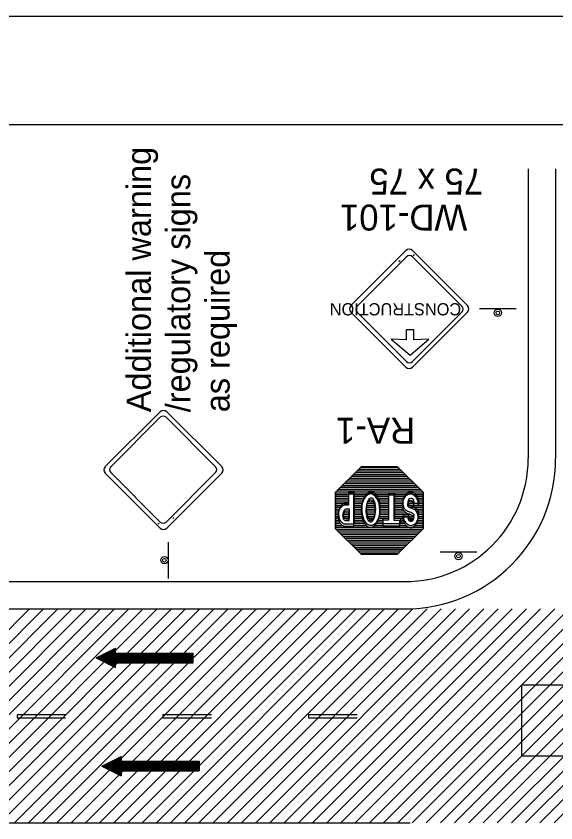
# Model space of a CAD drawing. Extents: x 2111 to 2327, y 208 to 487.
# Drawn here: x 2160.6 to 2214.3, y 406.9 to 487.2 of the extents above; entities that cross this region are included whole.
import ezdxf

# ---------------------------------------------------------------- set-up
doc = ezdxf.new("R2010")
doc.units = 0
for name, color, linetype in [('Level 10', 7, 'Continuous'), ('Level 2', 7, 'Continuous'), ('Level 44', 7, 'Continuous'), ('Level 60', 7, 'Continuous')]:
    doc.layers.add(name, color=color, linetype=linetype)

msp = doc.modelspace()

# ---------------------------------------------------------------- linework, layer by layer
at = {"layer": 'Level 10'}
for p, q in [((2211.547, 472.013), (2211.547, 443.162)), ((2214.274, 472.013), (2214.274, 443.162)), ((2140.664, 430.889), (2199.274, 430.889)), ((2140.664, 428.162), (2199.274, 428.162)), ((2140.664, 406.949), (2161.877, 428.162)), ((2141.991, 406.862), (2163.291, 428.162)), ((2143.406, 406.862), (2164.706, 428.162)), ((2144.82, 406.862), (2166.12, 428.162)), ((2146.234, 406.862), (2167.534, 428.162)), ((2147.649, 406.862), (2168.948, 428.162)), ((2149.063, 406.862), (2170.362, 428.162)), ((2150.477, 406.863), (2171.777, 428.162)), ((2151.892, 406.863), (2173.191, 428.162)), ((2153.306, 406.863), (2174.605, 428.162)), ((2154.72, 406.863), (2176.019, 428.162)), ((2156.134, 406.863), (2177.434, 428.162)), ((2157.549, 406.863), (2178.848, 428.162)), ((2158.963, 406.863), (2180.262, 428.162)), ((2160.377, 406.863), (2181.676, 428.162)), ((2161.792, 406.863), (2183.09, 428.162)), ((2163.206, 406.863), (2184.505, 428.162)), ((2164.62, 406.863), (2185.919, 428.162)), ((2166.034, 406.863), (2187.333, 428.162)), ((2167.449, 406.864), (2188.747, 428.162)), ((2168.863, 406.864), (2190.161, 428.162)), ((2170.277, 406.864), (2191.576, 428.162)), ((2171.692, 406.864), (2192.99, 428.162)), ((2173.106, 406.864), (2194.404, 428.162)), ((2174.52, 406.864), (2195.818, 428.162)), ((2175.935, 406.864), (2197.233, 428.162)), ((2177.349, 406.864), (2198.647, 428.162)), ((2178.763, 406.864), (2200.061, 428.162)), ((2180.177, 406.864), (2201.475, 428.162)), ((2181.592, 406.864), (2202.889, 428.162)), ((2183.006, 406.864), (2204.304, 428.162)), ((2184.42, 406.864), (2205.718, 428.162)), ((2185.835, 406.865), (2207.132, 428.162)), ((2187.249, 406.865), (2208.546, 428.162)), ((2188.663, 406.865), (2209.96, 428.162)), ((2190.077, 406.865), (2211.375, 428.162)), ((2191.492, 406.865), (2212.789, 428.162)), ((2192.906, 406.865), (2214.203, 428.162)), ((2194.32, 406.865), (2215.617, 428.162)), ((2195.735, 406.865), (2217.032, 428.162)), ((2197.149, 406.865), (2218.446, 428.162)), ((2198.563, 406.865), (2219.86, 428.162)), ((2199.978, 406.865), (2221.274, 428.162)), ((2201.392, 406.865), (2222.688, 428.162)), ((2202.806, 406.865), (2224.103, 428.162)), ((2204.22, 406.866), (2225.517, 428.162)), ((2205.635, 406.866), (2226.931, 428.162)), ((2207.049, 406.866), (2228.345, 428.162)), ((2208.463, 406.866), (2229.759, 428.162)), ((2209.878, 406.866), (2231.174, 428.162)), ((2211.292, 406.866), (2232.588, 428.162)), ((2212.706, 406.866), (2234.002, 428.162)), ((2214.12, 406.866), (2235.416, 428.162)), ((2168.514, 423.287), (2170.45, 424.255)), ((2170.45, 423.772), (2170.45, 424.255)), ((2168.999, 423.528), (2178.192, 423.528)), ((2169.241, 423.651), (2178.192, 423.651)), ((2169.482, 423.772), (2178.192, 423.772)), ((2169.724, 423.891), (2170.45, 423.891)), ((2169.966, 424.014), (2170.45, 424.014)), ((2170.208, 424.134), (2170.45, 424.134)), ((2170.45, 423.772), (2178.192, 423.772)), ((2178.192, 422.803), (2178.192, 423.772)), ((2168.514, 423.287), (2178.192, 423.287)), ((2168.514, 423.287), (2170.45, 422.32)), ((2168.757, 423.408), (2178.192, 423.408)), ((2168.757, 423.166), (2178.192, 423.166)), ((2168.999, 423.045), (2178.192, 423.045)), ((2169.241, 422.924), (2178.192, 422.924)), ((2169.482, 422.803), (2178.192, 422.803)), ((2169.724, 422.682), (2170.45, 422.682)), ((2170.45, 422.803), (2178.192, 422.803)), ((2170.45, 422.32), (2170.45, 422.803)), ((2169.966, 422.561), (2170.45, 422.561)), ((2170.208, 422.44), (2170.45, 422.44)), ((2169.092, 412.517), (2171.029, 413.486)), ((2170.06, 413), (2178.77, 413)), ((2170.302, 413.121), (2171.029, 413.121)), ((2170.544, 413.242), (2171.029, 413.242)), ((2170.785, 413.363), (2171.029, 413.363)), ((2171.029, 413.486), (2171.029, 413)), ((2171.029, 413), (2178.77, 413)), ((2178.77, 413), (2178.77, 412.033)), ((2169.092, 412.517), (2178.77, 412.517)), ((2169.092, 412.517), (2171.029, 411.548)), ((2169.335, 412.638), (2178.77, 412.638)), ((2169.335, 412.396), (2178.77, 412.396)), ((2169.577, 412.759), (2178.77, 412.759)), ((2169.577, 412.275), (2178.77, 412.275)), ((2169.818, 412.88), (2178.77, 412.88)), ((2169.818, 412.154), (2178.77, 412.154)), ((2170.06, 412.033), (2178.77, 412.033)), ((2170.302, 411.911), (2171.029, 411.911)), ((2170.544, 411.792), (2171.029, 411.792)), ((2170.785, 411.671), (2171.029, 411.671)), ((2171.029, 412.033), (2178.77, 412.033)), ((2171.029, 412.033), (2171.029, 411.548)), ((2140.664, 406.862), (2199.804, 406.862))]:
    msp.add_line(p, q, dxfattribs=at)
msp.add_lwpolyline([(2210.93, 420.618), (2238.784, 420.618), (2238.784, 413.503), (2210.93, 413.503)], close=True, dxfattribs=at)
for radius in [15, 12.273]:
    msp.add_arc((2199.274, 443.162), radius, 270, 0, dxfattribs=at)
at = {"layer": 'Level 2'}
for p, q in [((2198.682, 462.782), (2198.786, 462.886)), ((2200.136, 463.348), (2200.24, 463.452)), ((2176.247, 437.283), (2176.143, 437.179)), ((2174.793, 436.717), (2174.689, 436.613)), ((2165.481, 417.621), (2160.643, 417.621)), ((2160.643, 417.621), (2160.643, 417.331)), ((2160.643, 417.331), (2165.481, 417.331)), ((2179.995, 417.621), (2175.157, 417.621)), ((2175.157, 417.621), (2175.157, 417.331)), ((2175.157, 417.331), (2179.995, 417.331)), ((2194.509, 417.621), (2189.671, 417.621)), ((2189.671, 417.621), (2189.671, 417.331)), ((2189.671, 417.331), (2194.509, 417.331))]:
    msp.add_line(p, q, dxfattribs=at)
at = {"layer": 'Level 44'}
for p, q in [((2199.372, 463.855), (2193.902, 458.377)), ((2205.5, 458.377), (2200.02, 463.855)), ((2194.512, 458.317), (2199.438, 463.245)), ((2200.02, 463.245), (2204.952, 458.317)), ((2205.496, 458.377), (2205.5, 458.377)), ((2210.346, 458.06), (2206.716, 458.06)), ((2193.902, 457.727), (2199.372, 452.256)), ((2199.438, 452.807), (2194.512, 457.732)), ((2204.952, 457.732), (2200.02, 452.807)), ((2200.02, 452.256), (2205.5, 457.727)), ((2199.402, 455.965), (2199.402, 454.96)), ((2200.156, 455.965), (2199.406, 455.965)), ((2200.156, 454.96), (2200.156, 455.965)), ((2199.402, 454.96), (2197.896, 455.041)), ((2197.896, 455.041), (2199.778, 453.454)), ((2199.778, 453.454), (2201.662, 455.041)), ((2201.662, 455.041), (2200.156, 454.96)), ((2174.909, 447.809), (2169.429, 442.338)), ((2181.027, 442.338), (2175.557, 447.809)), ((2169.977, 442.333), (2174.909, 447.258)), ((2175.491, 447.258), (2180.417, 442.333)), ((2194.9, 442.333), (2192.352, 439.785)), ((2198.53, 442.333), (2194.9, 442.333)), ((2201.078, 439.785), (2198.53, 442.333)), ((2169.429, 441.688), (2174.909, 436.21)), ((2169.433, 441.688), (2169.429, 441.688)), ((2174.909, 436.82), (2169.977, 441.748)), ((2180.417, 441.748), (2175.491, 436.82)), ((2175.557, 436.21), (2181.027, 441.688)), ((2192.352, 439.785), (2192.352, 436.156)), ((2194.182, 439.596), (2193.652, 439.596)), ((2193.652, 439.596), (2193.652, 438.508)), ((2193.698, 438.719), (2193.698, 439.807)), ((2193.698, 439.807), (2194.228, 439.807)), ((2194.182, 436.403), (2194.182, 439.596)), ((2194.228, 439.807), (2194.228, 436.614)), ((2198.188, 439.502), (2197.636, 439.502)), ((2197.636, 439.502), (2197.636, 437.005)), ((2197.682, 439.713), (2198.234, 439.713)), ((2197.682, 437.216), (2197.682, 439.713)), ((2198.188, 436.991), (2198.188, 439.502)), ((2198.234, 439.713), (2198.234, 437.202)), ((2201.078, 436.156), (2201.078, 439.785)), ((2193.698, 438.719), (2193.364, 438.719)), ((2193.38, 438.711), (2193.698, 438.719)), ((2200.542, 439.314), (2200.544, 439.312)), ((2193.652, 438.508), (2193.318, 438.508)), ((2193.716, 437.905), (2193.376, 437.905)), ((2193.716, 437.905), (2193.376, 437.905)), ((2193.762, 438.116), (2193.422, 438.116)), ((2193.762, 438.116), (2193.422, 438.116)), ((2193.716, 436.976), (2193.716, 437.905)), ((2193.716, 436.976), (2193.716, 437.905)), ((2193.762, 437.187), (2193.762, 438.116)), ((2193.762, 437.187), (2193.762, 438.116)), ((2200.656, 438.471), (2200.156, 438.471)), ((2200.7, 438.682), (2200.2, 438.682)), ((2193.414, 437.187), (2193.762, 437.187)), ((2193.414, 437.187), (2193.762, 437.187)), ((2197.122, 436.643), (2197.122, 437.216)), ((2197.122, 437.216), (2197.682, 437.216)), ((2198.234, 437.202), (2198.822, 437.202)), ((2198.822, 437.202), (2198.822, 436.643)), ((2199.038, 437.325), (2199.582, 437.325)), ((2199.082, 437.536), (2199.628, 437.536)), ((2193.288, 436.403), (2194.182, 436.403)), ((2194.228, 436.614), (2193.334, 436.614)), ((2193.37, 436.976), (2193.716, 436.976)), ((2193.37, 436.976), (2193.716, 436.976)), ((2195.924, 436.502), (2195.908, 436.501)), ((2195.946, 437.045), (2195.924, 437.041)), ((2197.636, 437.005), (2197.078, 437.005)), ((2197.078, 437.005), (2197.078, 436.432)), ((2197.078, 436.432), (2198.776, 436.432)), ((2198.822, 436.643), (2197.122, 436.643)), ((2198.776, 436.991), (2198.188, 436.991)), ((2198.776, 436.432), (2198.776, 436.991)), ((2192.352, 436.156), (2194.9, 433.608)), ((2198.53, 433.608), (2201.078, 436.156)), ((2175.721, 431.196), (2175.721, 434.825)), ((2194.9, 433.608), (2198.53, 433.608)), ((2206.424, 433.831), (2202.796, 433.831))]:
    msp.add_line(p, q, dxfattribs=at)
msp.add_lwpolyline([(2192.352, 439.785), (2194.9, 442.333), (2198.53, 442.333), (2201.078, 439.785), (2201.078, 436.156), (2198.53, 433.608), (2194.9, 433.608), (2192.352, 436.156)], close=True, dxfattribs=at)
for points in [[(2198.782, 442.071), (2194.638, 442.071)], [(2198.61, 442.253), (2194.82, 442.253)], [(2199.698, 441.164), (2193.732, 441.164)], [(2199.516, 441.346), (2193.914, 441.346)], [(2199.334, 441.527), (2194.094, 441.527)], [(2199.154, 441.709), (2194.276, 441.709)], [(2198.972, 441.89), (2194.458, 441.89)], [(2200.424, 440.439), (2193.006, 440.439)], [(2200.242, 440.62), (2193.188, 440.62)], [(2200.062, 440.802), (2193.37, 440.802)], [(2199.88, 440.982), (2193.55, 440.982)], [(2201.078, 439.712), (2192.352, 439.712)], [(2193.652, 439.532), (2192.352, 439.532)], [(2200.968, 439.894), (2192.462, 439.894)], [(2200.786, 440.075), (2192.642, 440.075)], [(2200.604, 440.257), (2192.824, 440.257)], [(2195.576, 439.532), (2194.182, 439.532)], [(2199.538, 439.532), (2196.148, 439.532)], [(2201.078, 439.532), (2200.098, 439.532)], [(2193.652, 439.35), (2192.352, 439.35)], [(2193.652, 439.168), (2192.352, 439.168)], [(2193.652, 438.987), (2192.352, 438.987)], [(2193.652, 438.805), (2192.352, 438.805)], [(2195.358, 439.35), (2194.182, 439.35)], [(2195.226, 439.168), (2194.182, 439.168)], [(2195.132, 438.987), (2194.182, 438.987)], [(2195.06, 438.805), (2194.182, 438.805)], [(2196.126, 438.805), (2195.582, 438.805)], [(2197.636, 439.35), (2196.366, 439.35)], [(2197.636, 439.168), (2196.496, 439.168)], [(2197.636, 438.987), (2196.592, 438.987)], [(2197.636, 438.805), (2196.656, 438.805)], [(2199.298, 439.35), (2198.188, 439.35)], [(2199.168, 439.168), (2198.188, 439.168)], [(2199.082, 438.987), (2198.188, 438.987)], [(2199.022, 438.805), (2198.188, 438.805)], [(2200.082, 438.805), (2199.568, 438.805)], [(2201.078, 439.35), (2200.308, 439.35)], [(2201.078, 439.168), (2200.452, 439.168)], [(2201.078, 438.987), (2200.54, 438.987)], [(2201.078, 438.805), (2200.598, 438.805)], [(2193.652, 438.623), (2192.352, 438.623)], [(2193.122, 438.442), (2192.352, 438.442)], [(2192.876, 438.261), (2192.352, 438.261)], [(2192.752, 438.08), (2192.352, 438.08)], [(2192.686, 437.898), (2192.352, 437.898)], [(2195.01, 438.623), (2194.182, 438.623)], [(2194.974, 438.442), (2194.182, 438.442)], [(2194.944, 438.261), (2194.182, 438.261)], [(2194.93, 438.08), (2194.182, 438.08)], [(2194.922, 437.898), (2194.182, 437.898)], [(2196.324, 438.08), (2195.38, 438.08)], [(2196.324, 437.898), (2195.386, 437.898)], [(2196.302, 438.261), (2195.402, 438.261)], [(2196.266, 438.442), (2195.438, 438.442)], [(2196.208, 438.623), (2195.488, 438.623)], [(2197.636, 438.623), (2196.708, 438.623)], [(2197.636, 438.442), (2196.736, 438.442)], [(2197.636, 438.261), (2196.758, 438.261)], [(2197.636, 438.08), (2196.772, 438.08)], [(2197.636, 437.898), (2196.772, 437.898)], [(2199.008, 438.623), (2198.188, 438.623)], [(2199.008, 438.442), (2198.188, 438.442)], [(2199.038, 438.261), (2198.188, 438.261)], [(2199.088, 438.08), (2198.188, 438.08)], [(2199.226, 437.898), (2198.188, 437.898)], [(2200.14, 438.623), (2199.524, 438.623)], [(2201.078, 438.442), (2199.546, 438.442)], [(2201.078, 438.261), (2199.734, 438.261)], [(2201.078, 438.08), (2200.162, 438.08)], [(2201.078, 437.898), (2200.394, 437.898)], [(2201.078, 438.623), (2200.634, 438.623)], [(2192.636, 437.716), (2192.352, 437.716)], [(2192.614, 437.535), (2192.352, 437.535)], [(2192.622, 437.353), (2192.352, 437.353)], [(2192.642, 437.173), (2192.352, 437.173)], [(2193.724, 437.535), (2193.07, 437.535)], [(2193.716, 437.353), (2193.078, 437.353)], [(2193.716, 437.173), (2193.122, 437.173)], [(2193.716, 437.716), (2193.128, 437.716)], [(2194.938, 437.716), (2194.182, 437.716)], [(2194.95, 437.535), (2194.182, 437.535)], [(2194.988, 437.353), (2194.182, 437.353)], [(2195.032, 437.173), (2194.182, 437.173)], [(2196.308, 437.716), (2195.386, 437.716)], [(2196.302, 437.535), (2195.416, 437.535)], [(2196.25, 437.353), (2195.46, 437.353)], [(2196.2, 437.173), (2195.518, 437.173)], [(2197.636, 437.173), (2196.672, 437.173)], [(2197.636, 437.353), (2196.714, 437.353)], [(2197.636, 437.535), (2196.744, 437.535)], [(2197.63, 437.716), (2196.766, 437.716)], [(2199.474, 437.716), (2198.188, 437.716)], [(2199.88, 437.535), (2198.188, 437.535)], [(2200.112, 437.353), (2198.188, 437.353)], [(2199.046, 437.173), (2198.188, 437.173)], [(2200.14, 437.173), (2199.574, 437.173)], [(2201.078, 437.716), (2200.51, 437.716)], [(2201.078, 437.535), (2200.562, 437.535)], [(2201.078, 437.173), (2200.576, 437.173)], [(2201.078, 437.353), (2200.584, 437.353)], [(2192.686, 436.991), (2192.352, 436.991)], [(2192.774, 436.809), (2192.352, 436.809)], [(2192.89, 436.628), (2192.352, 436.628)], [(2193.122, 436.446), (2192.352, 436.446)], [(2193.716, 436.991), (2193.296, 436.991)], [(2195.096, 436.991), (2194.182, 436.991)], [(2195.176, 436.809), (2194.182, 436.809)], [(2195.292, 436.628), (2194.182, 436.628)], [(2195.466, 436.446), (2194.182, 436.446)], [(2196.112, 436.991), (2195.604, 436.991)], [(2197.078, 436.446), (2196.236, 436.446)], [(2197.078, 436.628), (2196.402, 436.628)], [(2197.078, 436.809), (2196.526, 436.809)], [(2197.078, 436.991), (2196.606, 436.991)], [(2199.088, 436.991), (2198.776, 436.991)], [(2199.14, 436.809), (2198.776, 436.809)], [(2199.24, 436.628), (2198.776, 436.628)], [(2199.4, 436.446), (2198.776, 436.446)], [(2200.062, 436.991), (2199.654, 436.991)], [(2201.078, 436.446), (2200.234, 436.446)], [(2201.078, 436.628), (2200.386, 436.628)], [(2201.078, 436.809), (2200.49, 436.809)], [(2201.078, 436.991), (2200.54, 436.991)], [(2201.078, 436.265), (2192.352, 436.265)], [(2201.004, 436.083), (2192.426, 436.083)], [(2200.822, 435.902), (2192.606, 435.902)], [(2200.642, 435.721), (2192.788, 435.721)], [(2200.46, 435.539), (2192.97, 435.539)], [(2200.278, 435.358), (2193.152, 435.358)], [(2200.098, 435.176), (2193.334, 435.176)], [(2199.916, 434.994), (2193.514, 434.994)], [(2199.734, 434.813), (2193.696, 434.813)], [(2199.552, 434.632), (2193.876, 434.632)], [(2199.37, 434.451), (2194.066, 434.451)], [(2199.19, 434.269), (2194.24, 434.269)], [(2199.008, 434.087), (2194.422, 434.087)], [(2198.828, 433.906), (2194.61, 433.906)], [(2198.646, 433.724), (2194.784, 433.724)]]:
    msp.add_lwpolyline(points, dxfattribs=at)
for centre, radius in [((2208.524, 457.654), 0.363), ((2208.524, 457.654), 0.181), ((2175.316, 433.018), 0.363), ((2175.316, 433.018), 0.181), ((2204.603, 433.424), 0.363), ((2204.603, 433.424), 0.181)]:
    msp.add_circle(centre, radius, dxfattribs=at)
for centre, radius, start, end in [((2199.698, 463.528), 0.458, 45, 135), ((2199.73, 462.953), 0.412, 45, 135), ((2194.223, 458.053), 0.458, 135, 225), ((2194.803, 458.025), 0.412, 135, 225), ((2204.658, 458.025), 0.412, 315, 44.99999), ((2205.173, 458.053), 0.458, 315, 44.99999), ((2199.73, 453.098), 0.412, 225, 315), ((2199.698, 452.578), 0.458, 225, 315), ((2175.231, 447.487), 0.458, 45, 135), ((2175.199, 446.967), 0.412, 45, 135), ((2169.756, 442.012), 0.458, 135, 224.99999), ((2170.271, 442.04), 0.412, 135, 224.99999), ((2180.126, 442.04), 0.412, 315, 45), ((2180.706, 442.012), 0.458, 315, 45), ((2199.948, 438.772), 0.868, 113.14132, 144.99056), ((2199.993, 438.983), 0.868, 113.14132, 144.99056), ((2199.821, 439.066), 0.544, 52.05359, 112.73967), ((2199.866, 439.277), 0.544, 52.05359, 112.73967), ((2199.45, 438.537), 1.189, 28.41538, 53.65531), ((2199.495, 438.748), 1.189, 28.41538, 53.65531), ((2193.504, 437.949), 0.784, 106.60198, 119.80906), ((2193.347, 438.529), 0.184, 79.79086, 113.54187), ((2200.934, 438.547), 1.924, 171.24702, 183.9864), ((2200.483, 438.413), 1.512, 145.50918, 163.2894), ((2200.979, 438.758), 1.924, 171.24702, 183.9864), ((2200.528, 438.624), 1.512, 145.50918, 163.2894), ((2199.986, 438.62), 0.459, 146.25303, 178.73226), ((2199.924, 438.789), 0.355, 172.57609, 210.47756), ((2200.031, 438.831), 0.459, 146.25303, 178.73226), ((2199.836, 438.617), 0.345, 95.4374, 134.06255), ((2199.881, 438.828), 0.345, 95.4374, 134.06255), ((2199.809, 438.588), 0.372, 50.6966, 91.45728), ((2199.854, 438.799), 0.372, 50.6966, 91.45728), ((2199.758, 438.623), 0.382, 6.87276, 42.74491), ((2199.803, 438.834), 0.382, 6.87276, 42.74491), ((2199.445, 438.69), 0.761, 359.01715, 13.51721), ((2198.986, 438.397), 1.669, 2.38409, 24.95188), ((2199.031, 438.608), 1.669, 2.38409, 24.95188), ((2194.363, 437.357), 1.764, 158.31533, 168.66985), ((2194.006, 437.673), 1.35, 169.75207, 182.79164), ((2194.006, 437.673), 1.35, 169.75207, 182.79164), ((2194.408, 437.568), 1.764, 158.31533, 168.66985), ((2193.525, 437.695), 0.86, 138.29225, 158.60313), ((2193.525, 437.695), 0.86, 138.29225, 158.60313), ((2193.57, 437.906), 0.86, 138.29225, 158.60313), ((2193.57, 437.906), 0.86, 138.29225, 158.60313), ((2193.301, 437.941), 0.531, 115.38384, 142.61875), ((2193.346, 438.152), 0.531, 115.38384, 142.61875), ((2193.459, 437.738), 0.784, 106.60198, 119.80906), ((2193.584, 437.709), 0.464, 146.50855, 177.0313), ((2193.584, 437.709), 0.464, 146.50855, 177.0313), ((2193.45, 437.551), 0.361, 101.91914, 145.7868), ((2193.45, 437.551), 0.361, 101.91914, 145.7868), ((2193.495, 437.762), 0.361, 101.91914, 145.7868), ((2193.495, 437.762), 0.361, 101.91914, 145.7868), ((2193.302, 438.318), 0.184, 79.79086, 113.54187), ((2200.367, 438.551), 1.359, 185.90969, 201.9865), ((2200.412, 438.762), 1.359, 185.90969, 201.9865), ((2197.463, 436.455), 2.281, 39.47897, 43.42605), ((2197.508, 436.666), 2.281, 39.47897, 43.42605), ((2200.131, 438.843), 1.305, 226.24648, 247.92633), ((2200.176, 439.054), 1.305, 226.24648, 247.92633), ((2199.879, 438.578), 0.355, 172.57609, 210.47756), ((2199.891, 438.619), 0.387, 214.20826, 254.15525), ((2199.936, 438.83), 0.387, 214.20826, 254.15525), ((2197.576, 432.525), 6.134, 64.46241, 68.83121), ((2197.621, 432.736), 6.134, 64.46241, 68.83121), ((2199.4, 438.479), 0.761, 359.01715, 13.51721), ((2199.744, 437.36), 0.847, 20.4481, 55.11069), ((2199.789, 437.571), 0.847, 20.4481, 55.11069), ((2193.961, 437.462), 1.35, 169.75207, 182.79164), ((2193.961, 437.462), 1.35, 169.75207, 182.79164), ((2194.29, 437.495), 1.68, 183.39027, 195.65974), ((2194.335, 437.706), 1.68, 183.39027, 195.65974), ((2193.559, 437.451), 0.864, 193.06738, 213.76202), ((2193.588, 437.435), 0.52, 170.34165, 195.23421), ((2193.588, 437.435), 0.52, 170.34165, 195.23421), ((2193.539, 437.498), 0.464, 146.50855, 177.0313), ((2193.539, 437.498), 0.464, 146.50855, 177.0313), ((2193.57, 437.372), 0.489, 188.60306, 214.21696), ((2193.57, 437.372), 0.489, 188.60306, 214.21696), ((2193.633, 437.646), 0.52, 170.34165, 195.23421), ((2193.633, 437.646), 0.52, 170.34165, 195.23421), ((2193.615, 437.583), 0.489, 188.60306, 214.21696), ((2193.615, 437.583), 0.489, 188.60306, 214.21696), ((2193.423, 437.278), 0.315, 215.11978, 259.31166), ((2193.423, 437.278), 0.315, 215.11978, 259.31166), ((2193.468, 437.489), 0.315, 215.11978, 259.31166), ((2193.468, 437.489), 0.315, 215.11978, 259.31166), ((2200.421, 437.349), 1.381, 180.69518, 197.14515), ((2200.466, 437.56), 1.381, 180.69518, 197.14515), ((2200.113, 437.402), 0.998, 194.56402, 229.00631), ((2200.016, 437.257), 0.449, 170.44122, 219.32441), ((2200.061, 437.468), 0.449, 170.44122, 219.32441), ((2199.035, 435.868), 1.866, 57.98164, 70.97904), ((2199.08, 436.079), 1.866, 57.98164, 70.97904), ((2199.917, 437.414), 0.308, 227.30173, 289.01194), ((2199.849, 437.18), 0.294, 293.8064, 352.24074), ((2199.894, 437.391), 0.294, 293.8064, 352.24074), ((2199.883, 437.222), 0.268, 344.13099, 58.14758), ((2199.928, 437.433), 0.268, 344.13099, 58.14758), ((2199.227, 437.288), 1.355, 337.73321, 357.13918), ((2199.272, 437.499), 1.355, 337.73321, 357.13918), ((2199.395, 437.325), 1.19, 354.81715, 15.91834), ((2199.44, 437.536), 1.19, 354.81715, 15.91834), ((2175.199, 437.112), 0.412, 225, 315), ((2193.514, 437.24), 0.864, 193.06738, 213.76202), ((2193.503, 437.161), 0.814, 209.22414, 228.53082), ((2193.503, 437.161), 0.814, 209.22414, 228.53082), ((2193.548, 437.372), 0.814, 209.22414, 228.53082), ((2193.548, 437.372), 0.814, 209.22414, 228.53082), ((2193.337, 436.928), 0.53, 224.85284, 265.0441), ((2193.382, 437.139), 0.53, 224.85284, 265.0441), ((2200.068, 437.191), 0.998, 194.56402, 229.00631), ((2199.821, 436.867), 0.591, 226.13686, 301.39871), ((2199.866, 437.078), 0.591, 226.13686, 301.39871), ((2199.872, 437.203), 0.308, 227.30173, 289.01194), ((2199.599, 437.171), 0.967, 303.3662, 335.67344), ((2199.644, 437.382), 0.967, 303.3662, 335.67344), ((2175.231, 436.537), 0.458, 225, 315)]:
    msp.add_arc(centre, radius, start, end, dxfattribs=at)
for centre, major_axis, ratio, start_param, end_param in [((2195.85, 437.953), (0.011, 1.663), 0.558644, 3.185857, 9.451311), ((2195.895, 438.164), (0.011, 1.663), 0.558644, 4.129576, 6.939747), ((2195.895, 438.164), (0.011, 1.663), 0.558644, 0.656861, 3.168126), ((2195.85, 437.915), (-0.006, 1.086), 0.432619, 3.239639, 9.473919), ((2195.895, 438.126), (-0.006, 1.086), 0.432619, 0.881967, 3.190734), ((2195.895, 438.126), (-0.006, 1.086), 0.432619, 3.890436, 7.165085), ((2195.895, 438.164), (0.011, 1.663), 0.558644, 3.185857, 4.129398), ((2195.895, 438.126), (-0.006, 1.086), 0.432619, 3.239639, 3.888884)]:
    msp.add_ellipse(centre, major_axis=major_axis, ratio=ratio, start_param=start_param, end_param=end_param, dxfattribs=at)
at = {"layer": 'Level 60'}
for points in [[(2111.318, 487.207), (2327.318, 487.207), (2327.318, 208.207), (2111.318, 208.207)], [(2130.444, 476.398), (2317.318, 476.398), (2317.318, 219.016), (2130.444, 219.016)]]:
    msp.add_lwpolyline(points, close=True, dxfattribs=at)

# ---------------------------------------------------------------- texts
at = {"layer": 'Level 10'}
for s, height, rotation, p in [('Additional warning', 2.419, 90, (2173.97, 447.757)), ('75 x 75', 2.585, 180, (2207.068, 472.024)), ('/regulatory signs ', 2.419, 90, (2177.889, 447.757)), ('WD-101', 2.585, 180, (2205.479, 468.439)), ('as required', 2.419, 90, (2181.808, 447.757)), ('RA-1', 2.5853, 180, (2200.292, 447.205))]:
    msp.add_text(s, height=height, rotation=rotation, dxfattribs=at).set_placement(p)
at = {"layer": 'Level 44'}
msp.add_text('CONSTRUCTION', height=1.21481, rotation=180, dxfattribs=at).set_placement((2204.874, 458.62))

doc.saveas('drawing.dxf')
